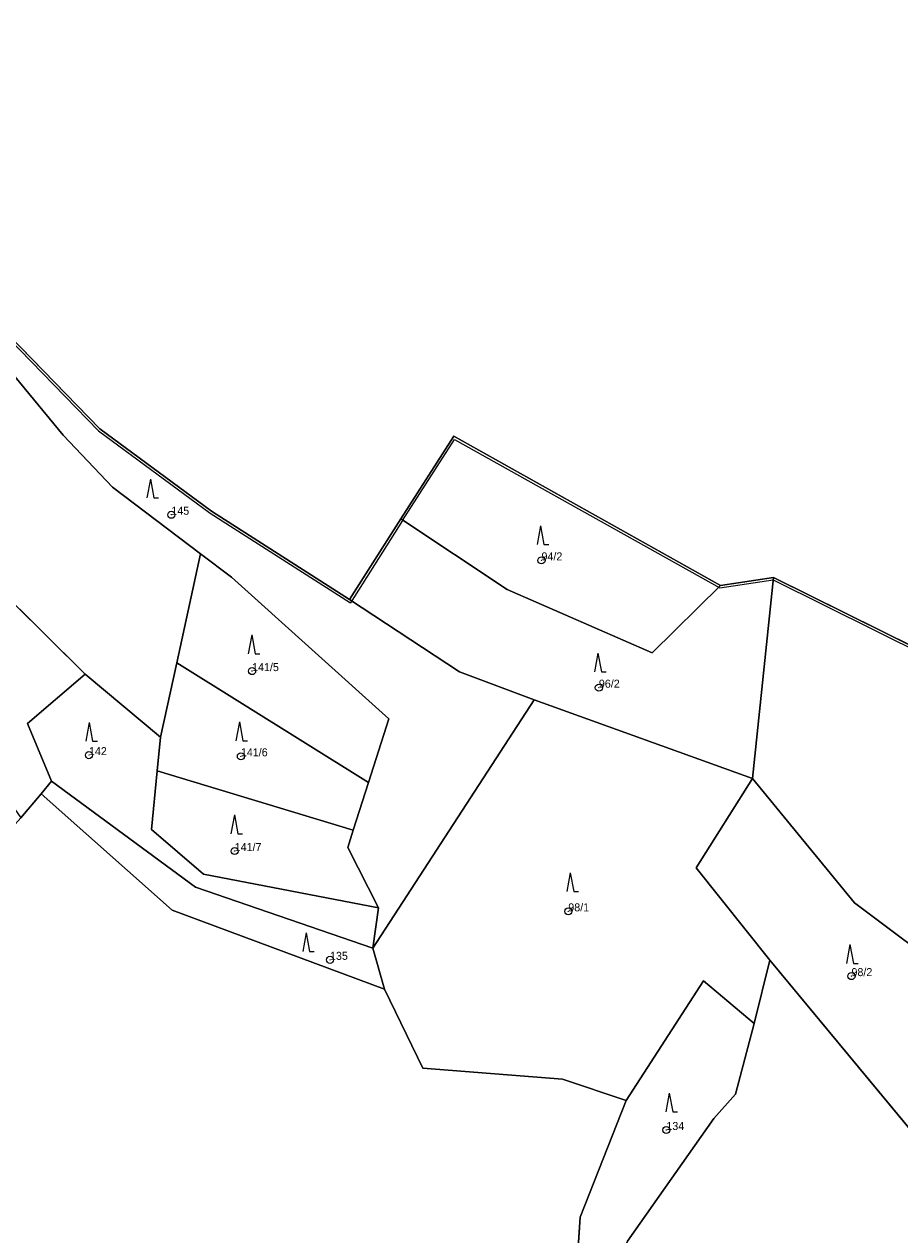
# Model space of a CAD drawing. Extents: x -652854 to -650068, y -1097661 to -1095417.
# Drawn here: x -650622.9 to -650437, y -1095838.2 to -1095581.1 of the extents above; entities that cross this region are included whole.
import ezdxf

# ---------------------------------------------------------------- set-up
doc = ezdxf.new("R2010")
doc.units = 0
for name, color, linetype in [('Definiční body parcel', 7, 'Continuous'), ('Hranice obcí', 7, 'Continuous'), ('Hranice parcel', 7, 'Continuous'), ('Obvody jako plochy', 7, 'Continuous'), ('Ostatní hranice', 7, 'Continuous'), ('Parcelní čísla', 7, 'Continuous'), ('Značky kultur', 7, 'Continuous')]:
    doc.layers.add(name, color=color, linetype=linetype)

msp = doc.modelspace()

# ---------------------------------------------------------------- linework, layer by layer
at = {"layer": 'Definiční body parcel'}
for centre, radius in [((-650591.67, -1095685.31), 0.75), ((-650591.67, -1095685.31), 0.0327), ((-650513.1, -1095695), 0.75), ((-650513.1, -1095695), 0.0327), ((-650574.53, -1095718.51), 0.75), ((-650574.53, -1095718.51), 0.0327), ((-650500.92, -1095722.03), 0.75), ((-650500.92, -1095722.03), 0.0327), ((-650609.16, -1095736.36), 0.75), ((-650576.91, -1095736.6), 0.75), ((-650609.16, -1095736.36), 0.0327), ((-650576.91, -1095736.6), 0.0327), ((-650578.22, -1095756.72), 0.75), ((-650578.22, -1095756.72), 0.0327), ((-650507.41, -1095769.53), 0.75), ((-650507.41, -1095769.53), 0.0327), ((-650557.99, -1095779.82), 0.75), ((-650557.99, -1095779.82), 0.0327), ((-650447.3, -1095783.28), 0.75), ((-650447.3, -1095783.28), 0.0327), ((-650486.59, -1095815.95), 0.75), ((-650486.59, -1095815.95), 0.0327)]:
    msp.add_circle(centre, radius, dxfattribs=at)
at = {"layer": 'Hranice obcí'}
for p, q in [((-650630.81, -1095642.44), (-650606.83, -1095667.07)), ((-650606.83, -1095667.07), (-650583.15, -1095684.58)), ((-650542.99, -1095686.21), (-650531.72, -1095668.65)), ((-650531.72, -1095668.65), (-650475.13, -1095700.3)), ((-650583.15, -1095684.58), (-650553.83, -1095703.34)), ((-650553.83, -1095703.34), (-650542.99, -1095686.21)), ((-650475.13, -1095700.3), (-650463.84, -1095698.61)), ((-650463.84, -1095698.61), (-650426.17, -1095717.32))]:
    msp.add_line(p, q, dxfattribs=at)
at = {"layer": 'Hranice parcel'}
for p, q in [((-650614.63, -1095668.43), (-650628.31, -1095651.9)), ((-650609.93, -1095719.17), (-650663.87, -1095665.77)), ((-650604.18, -1095679.45), (-650614.63, -1095668.43)), ((-650585.5, -1095693.58), (-650604.18, -1095679.45)), ((-650542.99, -1095686.21), (-650520.35, -1095701.21)), ((-650590.54, -1095716.72), (-650585.5, -1095693.58)), ((-650578.92, -1095698.55), (-650585.5, -1095693.58)), ((-650545.49, -1095728.66), (-650578.92, -1095698.55)), ((-650468.3, -1095741.3), (-650463.84, -1095698.61)), ((-650520.35, -1095701.21), (-650489.62, -1095714.61)), ((-650489.62, -1095714.61), (-650475.13, -1095700.3)), ((-650553.83, -1095703.34), (-650530.51, -1095718.67)), ((-650593.98, -1095732.55), (-650590.54, -1095716.72)), ((-650590.54, -1095716.72), (-650549.8, -1095742.14)), ((-650609.93, -1095719.17), (-650622.17, -1095729.62)), ((-650593.98, -1095732.55), (-650609.93, -1095719.17)), ((-650530.51, -1095718.67), (-650514.67, -1095724.6)), ((-650514.67, -1095724.6), (-650548.93, -1095777.36)), ((-650514.67, -1095724.6), (-650468.3, -1095741.3)), ((-650622.17, -1095729.62), (-650617.13, -1095741.88)), ((-650549.8, -1095742.14), (-650545.49, -1095728.66)), ((-650594.67, -1095739.66), (-650593.98, -1095732.55)), ((-650595.89, -1095752.12), (-650594.67, -1095739.66)), ((-650594.67, -1095739.66), (-650553.04, -1095752.26)), ((-650617.13, -1095741.88), (-650619.29, -1095744.55)), ((-650617.13, -1095741.88), (-650586.55, -1095764.4)), ((-650553.04, -1095752.26), (-650549.8, -1095742.14)), ((-650468.3, -1095741.3), (-650480.27, -1095760.26)), ((-650468.3, -1095741.3), (-650446.64, -1095767.71)), ((-650623.63, -1095749.68), (-650619.29, -1095744.55)), ((-650619.29, -1095744.55), (-650591.47, -1095769.26)), ((-650584.86, -1095761.62), (-650595.89, -1095752.12)), ((-650554.24, -1095756), (-650553.04, -1095752.26)), ((-650547.69, -1095768.77), (-650554.24, -1095756)), ((-650480.27, -1095760.26), (-650464.66, -1095779.87)), ((-650547.69, -1095768.77), (-650584.86, -1095761.62)), ((-650586.55, -1095764.4), (-650548.93, -1095777.36)), ((-650591.47, -1095769.26), (-650546.41, -1095786.02)), ((-650548.93, -1095777.36), (-650547.69, -1095768.77)), ((-650446.64, -1095767.71), (-650424.91, -1095783.97)), ((-650548.93, -1095777.36), (-650546.41, -1095786.02)), ((-650464.66, -1095779.87), (-650467.96, -1095793.34)), ((-650464.66, -1095779.87), (-650431.1, -1095820.4)), ((-650495.09, -1095809.68), (-650478.74, -1095784.29)), ((-650478.74, -1095784.29), (-650467.96, -1095793.34)), ((-650546.41, -1095786.02), (-650538.3, -1095802.8)), ((-650467.96, -1095793.34), (-650471.89, -1095808.33)), ((-650538.3, -1095802.8), (-650508.67, -1095805.16)), ((-650508.67, -1095805.16), (-650495.09, -1095809.68)), ((-650504.91, -1095834.49), (-650495.09, -1095809.68)), ((-650471.89, -1095808.33), (-650476.53, -1095813.53)), ((-650476.53, -1095813.53), (-650494.84, -1095839.58)), ((-650505.7, -1095846.33), (-650504.91, -1095834.49))]:
    msp.add_line(p, q, dxfattribs=at)
at = {"layer": 'Obvody jako plochy'}
for points in [[(-650782.47, -1095579.91), (-650748.84, -1095611.39), (-650738.08, -1095601.78), (-650716.05, -1095622.63), (-650711.08, -1095616.78), (-650710.13, -1095615.6), (-650684.56, -1095627.98), (-650658.11, -1095653.13), (-650658.07, -1095655.6), (-650663.87, -1095665.77), (-650609.93, -1095719.17), (-650593.98, -1095732.55), (-650590.54, -1095716.72), (-650585.5, -1095693.58), (-650604.18, -1095679.45), (-650614.63, -1095668.43), (-650628.31, -1095651.9), (-650650.68, -1095630.97), (-650669.48, -1095610.17), (-650683.44, -1095582.32), (-650726.87, -1095568.17)], [(-650505.7, -1095846.33), (-650504.91, -1095834.49), (-650495.09, -1095809.68), (-650508.67, -1095805.16), (-650538.3, -1095802.8), (-650546.41, -1095786.02), (-650591.47, -1095769.26), (-650619.29, -1095744.55), (-650623.63, -1095749.68), (-650625.37, -1095751.64), (-650633.88, -1095755.89), (-650645.07, -1095735.22), (-650668.63, -1095706.14), (-650675.04, -1095715.85), (-650692.25, -1095742.86), (-650709.03, -1095779.57), (-650699.64, -1095816.89), (-650707.4, -1095814.79), (-650739.26, -1095845.66)]]:
    msp.add_lwpolyline(points, dxfattribs=at)
for points in [[(-650654.04, -1095616.92), (-650683.44, -1095582.32), (-650669.48, -1095610.17), (-650650.68, -1095630.97), (-650628.31, -1095651.9), (-650614.63, -1095668.43), (-650604.18, -1095679.45), (-650585.5, -1095693.58), (-650578.92, -1095698.55), (-650545.49, -1095728.66), (-650549.8, -1095742.14), (-650553.04, -1095752.26), (-650554.24, -1095756), (-650547.69, -1095768.77), (-650548.93, -1095777.36), (-650514.67, -1095724.6), (-650530.51, -1095718.67), (-650553.83, -1095703.34), (-650583.15, -1095684.58), (-650606.83, -1095667.07), (-650630.81, -1095642.44)], [(-650609.93, -1095719.17), (-650663.87, -1095665.77), (-650672.04, -1095679.42), (-650657.28, -1095701.2), (-650641.16, -1095724.38), (-650623.63, -1095749.68), (-650619.29, -1095744.55), (-650617.13, -1095741.88), (-650622.17, -1095729.62)], [(-650542.99, -1095686.21), (-650520.35, -1095701.21), (-650489.62, -1095714.61), (-650475.13, -1095700.3), (-650531.72, -1095668.65)], [(-650542.99, -1095686.21), (-650553.83, -1095703.34), (-650530.51, -1095718.67), (-650514.67, -1095724.6), (-650468.3, -1095741.3), (-650463.84, -1095698.61), (-650475.13, -1095700.3), (-650489.62, -1095714.61), (-650520.35, -1095701.21)], [(-650545.49, -1095728.66), (-650578.92, -1095698.55), (-650585.5, -1095693.58), (-650590.54, -1095716.72), (-650549.8, -1095742.14)], [(-650411.23, -1095692.93), (-650426.17, -1095717.32), (-650463.84, -1095698.61), (-650468.3, -1095741.3), (-650446.64, -1095767.71), (-650424.91, -1095783.97), (-650406.4, -1095756.55), (-650384.69, -1095723.07), (-650391.37, -1095719.95), (-650390.82, -1095710.69), (-650396.11, -1095707.5), (-650393.28, -1095702.87), (-650399.21, -1095699.18)], [(-650594.67, -1095739.66), (-650553.04, -1095752.26), (-650549.8, -1095742.14), (-650590.54, -1095716.72), (-650593.98, -1095732.55)], [(-650593.98, -1095732.55), (-650609.93, -1095719.17), (-650622.17, -1095729.62), (-650617.13, -1095741.88), (-650586.55, -1095764.4), (-650548.93, -1095777.36), (-650547.69, -1095768.77), (-650584.86, -1095761.62), (-650595.89, -1095752.12), (-650594.67, -1095739.66)], [(-650538.3, -1095802.8), (-650508.67, -1095805.16), (-650495.09, -1095809.68), (-650478.74, -1095784.29), (-650467.96, -1095793.34), (-650464.66, -1095779.87), (-650480.27, -1095760.26), (-650468.3, -1095741.3), (-650514.67, -1095724.6), (-650548.93, -1095777.36), (-650546.41, -1095786.02)], [(-650547.69, -1095768.77), (-650554.24, -1095756), (-650553.04, -1095752.26), (-650594.67, -1095739.66), (-650595.89, -1095752.12), (-650584.86, -1095761.62)], [(-650617.13, -1095741.88), (-650619.29, -1095744.55), (-650591.47, -1095769.26), (-650546.41, -1095786.02), (-650548.93, -1095777.36), (-650586.55, -1095764.4)], [(-650420.14, -1095787.7), (-650424.91, -1095783.97), (-650446.64, -1095767.71), (-650468.3, -1095741.3), (-650480.27, -1095760.26), (-650464.66, -1095779.87), (-650431.1, -1095820.4), (-650406.15, -1095791.32)], [(-650406.15, -1095791.32), (-650431.1, -1095820.4), (-650464.66, -1095779.87), (-650467.96, -1095793.34), (-650471.89, -1095808.33), (-650476.53, -1095813.53), (-650494.84, -1095839.58), (-650499.26, -1095849.08), (-650487.46, -1095903.53), (-650470.26, -1095905.62), (-650456.75, -1095891.76), (-650441.52, -1095882.55), (-650432.6, -1095881.88), (-650408.98, -1095891.11), (-650398.66, -1095892.26), (-650382.62, -1095893.79), (-650374.95, -1095883.69), (-650389.75, -1095872.8), (-650399.87, -1095862.15), (-650409.55, -1095851.54), (-650415.8, -1095834.87), (-650412.7, -1095808.67), (-650404.41, -1095793.36), (-650405.21, -1095790.46)], [(-650494.84, -1095839.58), (-650476.53, -1095813.53), (-650471.89, -1095808.33), (-650467.96, -1095793.34), (-650478.74, -1095784.29), (-650495.09, -1095809.68), (-650504.91, -1095834.49), (-650505.7, -1095846.33), (-650511.07, -1095852.45), (-650499.26, -1095849.08)]]:
    msp.add_lwpolyline(points, close=True, dxfattribs=at)
at = {"layer": 'Ostatní hranice'}
for p, q in [((-650631.17, -1095642.8), (-650607.14, -1095667.48)), ((-650607.14, -1095667.48), (-650583.45, -1095684.99)), ((-650542.59, -1095686.53), (-650531.55, -1095669.33)), ((-650531.55, -1095669.33), (-650475.24, -1095700.82)), ((-650583.45, -1095684.99), (-650553.66, -1095704.04)), ((-650542.59, -1095686.53), (-650553.66, -1095704.04)), ((-650475.24, -1095700.82), (-650463.94, -1095699.11)), ((-650463.94, -1095699.11), (-650425.98, -1095717.98))]:
    msp.add_line(p, q, dxfattribs=at)
at = {"layer": 'Značky kultur'}
for p, q in [((-650596.122, -1095677.739), (-650596.855, -1095681.739)), ((-650596.122, -1095677.739), (-650595.389, -1095681.739)), ((-650595.389, -1095681.739), (-650594.389, -1095681.739)), ((-650513.302, -1095687.659), (-650514.035, -1095691.659)), ((-650513.302, -1095687.659), (-650512.569, -1095691.659)), ((-650512.569, -1095691.659), (-650511.569, -1095691.659)), ((-650574.602, -1095710.839), (-650575.335, -1095714.839)), ((-650574.602, -1095710.839), (-650573.869, -1095714.839)), ((-650573.869, -1095714.839), (-650572.869, -1095714.839)), ((-650501.122, -1095714.699), (-650501.855, -1095718.699)), ((-650501.122, -1095714.699), (-650500.389, -1095718.699)), ((-650500.389, -1095718.699), (-650499.389, -1095718.699)), ((-650609.112, -1095729.409), (-650609.845, -1095733.409)), ((-650609.112, -1095729.409), (-650608.379, -1095733.409)), ((-650577.222, -1095729.289), (-650577.955, -1095733.289)), ((-650577.222, -1095729.289), (-650576.489, -1095733.289)), ((-650576.489, -1095733.289), (-650575.489, -1095733.289)), ((-650608.379, -1095733.409), (-650607.379, -1095733.409)), ((-650578.292, -1095749.049), (-650579.025, -1095753.049)), ((-650578.292, -1095749.049), (-650577.559, -1095753.049)), ((-650577.559, -1095753.049), (-650576.559, -1095753.049)), ((-650506.992, -1095761.319), (-650507.725, -1095765.319)), ((-650506.992, -1095761.319), (-650506.259, -1095765.319)), ((-650506.259, -1095765.319), (-650505.259, -1095765.319)), ((-650563.052, -1095774.059), (-650563.785, -1095778.059)), ((-650563.052, -1095774.059), (-650562.319, -1095778.059)), ((-650447.612, -1095776.599), (-650448.345, -1095780.599)), ((-650447.612, -1095776.599), (-650446.879, -1095780.599)), ((-650562.319, -1095778.059), (-650561.319, -1095778.059)), ((-650446.879, -1095780.599), (-650445.879, -1095780.599)), ((-650485.982, -1095808.119), (-650486.715, -1095812.119)), ((-650485.982, -1095808.119), (-650485.249, -1095812.119)), ((-650485.249, -1095812.119), (-650484.249, -1095812.119))]:
    msp.add_line(p, q, dxfattribs=at)

# ---------------------------------------------------------------- texts
at = {"layer": 'Parcelní čísla'}
for s, p in [('145', (-650591.67, -1095685.31)), ('94/2', (-650513.1, -1095695)), ('141/5', (-650574.53, -1095718.51)), ('96/2', (-650500.92, -1095722.03)), ('142', (-650609.16, -1095736.36)), ('141/6', (-650576.91, -1095736.6)), ('141/7', (-650578.22, -1095756.72)), ('98/1', (-650507.41, -1095769.53)), ('135', (-650557.99, -1095779.82)), ('98/2', (-650447.3, -1095783.28)), ('134', (-650486.59, -1095815.95))]:
    msp.add_text(s, height=1.7, dxfattribs=at).set_placement(p)

doc.saveas('drawing.dxf')
